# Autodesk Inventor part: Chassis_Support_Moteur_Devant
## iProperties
Created: 2008-12
Part Number: Chassis_Support_Moteur_Devant
Document SubType Name: Sheet Metal
Designer: claivier
Author: claivier
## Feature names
1. Extrusion1
2. Extrusion2
3. Extrusion3
4. Extrusion4
5. Extrusion5
6. Chanfrein1 [Chamfer]
7. Perçage1 [Hole]
8. Perçage2 [Hole]
9. Miroir1 [Mirror]
10. Perçage3 [Hole]
11. Perçage4 [Hole]
12. Perçage5 [Hole]
13. Extrusion6
14. Miroir2 [Mirror]
15. Perçage6 [Hole]
16. Perçage7 [Hole]
17. Plaque1
18. Pli1
